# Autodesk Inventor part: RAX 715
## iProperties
Author: robert
Shininess: 20.0
Angle Display Precision: 2
Document Length Units: 11269
Document Angle Units: 11283
Document Time Units: 11279
Document Mass Units: 11290
Document Length Units Precision: 3
Document Angle Units Precision: 2
Compacted: True
PropertySet Name: _Private Model Information
Created: 2002-06
Part Number: RAX 715
Material: Par défaut
Document SubType Name: Modélisation
Designer: robert
Control State: 0
Master: False
Checked Out: False
PropertySet Name: Design Tracking Control
Density: 0.0
Volumn: 0.0
Area: 0.0
PropertySet Name: Model Information
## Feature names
1. Révolution1 [Revolution]
2. Révolution2 [Revolution]
3. Révolution3 [Revolution]
4. Réseau circulaire1 [Circular Pattern]
